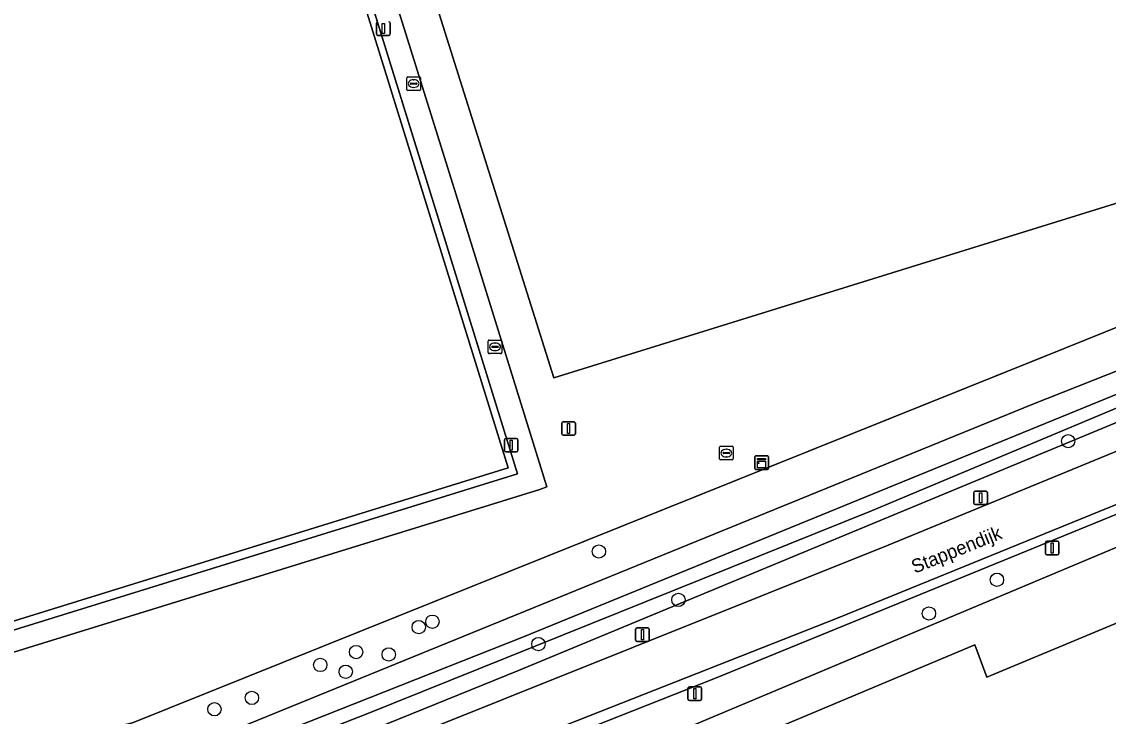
# Model space of a CAD drawing. Extents: x 161090 to 161692, y 379509 to 380907.
# Drawn here: x 161308.9 to 161388.6, y 379764.3 to 379815.2 of the extents above; entities that cross this region are included whole.
import ezdxf

# ---------------------------------------------------------------- set-up
doc = ezdxf.new("R2010")
doc.units = 0
for name, color, linetype in [('IMGEO_Boom', 7, 'Continuous'), ('IMGEO_Fietspad_gesloten', 7, 'Continuous'), ('IMGEO_Groenvoorziening', 7, 'Continuous'), ('IMGEO_Hek', 7, 'Continuous'), ('IMGEO_Kast', 7, 'Continuous'), ('IMGEO_Kolk', 7, 'Continuous'), ('IMGEO_Lichtmast', 7, 'Continuous'), ('IMGEO_Oever', 7, 'Continuous'), ('IMGEO_Openbare_ruimte_label', 7, 'Continuous'), ('IMGEO_Parkeervlak_gesloten', 7, 'Continuous'), ('IMGEO_Rijbaan_lokaal_gesloten', 7, 'Continuous'), ('IMGEO_Rioolput', 7, 'Continuous'), ('IMGEO_Terreindeel_open', 7, 'Continuous'), ('IMGEO_Voetpad_open', 7, 'Continuous'), ('IMGEO_Waterloop', 7, 'Continuous')]:
    doc.layers.add(name, color=color, linetype=linetype)

msp = doc.modelspace()

# ---------------------------------------------------------------- linework, layer by layer
at = {"layer": 'IMGEO_Boom'}
for centre in [(161385.637, 379784.44), (161351.238, 379776.349), (161380.42, 379774.272), (161357.066, 379772.8), (161375.433, 379771.801), (161339.03, 379771.2), (161338.031, 379770.803), (161346.802, 379769.558), (161333.443, 379768.976), (161335.83, 379768.8), (161330.817, 379768.025), (161332.677, 379767.53), (161325.801, 379765.614), (161323.059, 379764.777)]:
    msp.add_circle(centre, 0.489, dxfattribs=at)
at = {"layer": 'IMGEO_Fietspad_gesloten'}
for points in [[(161217.63, 379728.601), (161261.386, 379738.685), (161308.111, 379750), (161320.623, 379753.03), (161330.613, 379756.284), (161333.8, 379757.687), (161368.776, 379771.487), (161387.909, 379779.27), (161415.666, 379790.561)], [(161407.443, 379791.212), (161386.356, 379782.534), (161372.453, 379776.813), (161325.661, 379758.067), (161323.089, 379757.248), (161318.2, 379756.091), (161302.182, 379751.792), (161294.533, 379750), (161230.315, 379734.955)]]:
    msp.add_lwpolyline(points, dxfattribs=at)
at = {"layer": 'IMGEO_Groenvoorziening'}
for points in [[(161407.333, 379882.123), (161377.631, 379872.865), (161377.083, 379874.601), (161374.902, 379873.923), (161375.596, 379871.724), (161373.493, 379871.07), (161372.799, 379873.269), (161370.509, 379872.557), (161371.048, 379870.8), (161341.341, 379861.559), (161340.782, 379863.315), (161333.233, 379860.926), (161323.473, 379857.884), (161325.421, 379851.624), (161340.534, 379803.282), (161347.426, 379781.085), (161346.908, 379780.9), (161282.797, 379761.057), (161284.027, 379756.207), (161284.135, 379755.78), (161317.062, 379763.781), (161383.819, 379790.615), (161442.415, 379814.263)], [(161442.415, 379814.263), (161383.819, 379790.615), (161317.062, 379763.781), (161284.135, 379755.78), (161259.936, 379750), (161224.74, 379740.671)], [(161321.194, 379761.932), (161383.047, 379787.15), (161437.336, 379808.629), (161438.26, 379805.933), (161414.978, 379796.508), (161345.338, 379767.612), (161322.581, 379758.384), (161307.399, 379754.371), (161244.228, 379739.369), (161215.479, 379732.972)], [(161180.807, 379761.477), (161184.615, 379755.126), (161189.385, 379745.645), (161194.335, 379735.113), (161197.105, 379730.453), (161201.159, 379723.634), (161202.937, 379724.063), (161210.481, 379725.863), (161210.245, 379726.978), (161204.585, 379725.735), (161202.141, 379725.056), (161199.88, 379730.004), (161200.37, 379730.456), (161211.43, 379731.076), (161230.315, 379734.955), (161294.533, 379750), (161302.182, 379751.792), (161318.2, 379756.091), (161323.089, 379757.248), (161325.661, 379758.067), (161372.453, 379776.813), (161386.356, 379782.534), (161407.443, 379791.212)], [(161415.916, 379790.022), (161359.784, 379767.053), (161334.748, 379757.161), (161323.449, 379753.122), (161314.492, 379750.449), (161260.228, 379737.49), (161228.423, 379730.143), (161214.473, 379726.815), (161214.755, 379725.892), (161216.77, 379726.358), (161281.548, 379741.341), (161281.646, 379741.364), (161304.908, 379746.911), (161319.404, 379750.447), (161326.887, 379752.243), (161336.716, 379754.602), (161350.416, 379760.36), (161396.996, 379779.937)]]:
    msp.add_lwpolyline(points, dxfattribs=at)
for points in [[(161420.503, 379878.307), (161328.846, 379849.835), (161338.143, 379820.234), (161347.925, 379789.089), (161439.346, 379817.487)], [(161439.346, 379817.487), (161347.925, 379789.089), (161338.143, 379820.234), (161328.846, 379849.835), (161420.503, 379878.307)], [(161214.16, 379727.839), (161214.473, 379726.815), (161228.423, 379730.143), (161260.228, 379737.49), (161314.492, 379750.449), (161323.449, 379753.122), (161334.748, 379757.161), (161359.784, 379767.053), (161415.916, 379790.022), (161415.666, 379790.561), (161387.909, 379779.27), (161368.776, 379771.487), (161333.8, 379757.687), (161330.613, 379756.284), (161320.623, 379753.03), (161308.111, 379750), (161261.386, 379738.685), (161217.63, 379728.601)]]:
    msp.add_lwpolyline(points, close=True, dxfattribs=at)
at = {"layer": 'IMGEO_Hek'}
for points in [[(161315.726, 379877.436), (161345.273, 379782.041)], [(161437.337, 379812.165), (161426.879, 379807.924), (161317.062, 379763.781)], [(161415.916, 379790.022), (161359.784, 379767.053), (161334.748, 379757.161), (161323.449, 379753.122), (161314.492, 379750.449), (161260.228, 379737.49), (161228.423, 379730.143), (161214.473, 379726.815)], [(161345.273, 379782.041), (161288.749, 379764.513)]]:
    msp.add_lwpolyline(points, dxfattribs=at)
at = {"layer": 'IMGEO_Kast'}
for p, q in [((161362.74, 379783.367), (161363.581, 379783.367)), ((161363.581, 379783.367), (161362.74, 379783.367)), ((161362.665, 379782.442), (161362.665, 379783.283)), ((161362.665, 379783.283), (161362.665, 379782.442)), ((161363.665, 379783.292), (161363.665, 379782.451)), ((161363.665, 379782.451), (161363.665, 379783.292)), ((161363.59, 379782.367), (161362.749, 379782.367)), ((161362.749, 379782.367), (161363.59, 379782.367))]:
    msp.add_line(p, q, dxfattribs=at)
for points in [[(161362.86, 379783.157), (161363.46, 379783.157), (161363.46, 379783.072), (161362.86, 379783.072), (161362.86, 379783.157)], [(161362.86, 379782.982), (161363.46, 379782.982), (161363.46, 379782.493), (161362.86, 379782.493), (161362.86, 379782.982)]]:
    msp.add_lwpolyline(points, dxfattribs=at)
msp.add_circle((161362.944, 379782.831), 0.0377, dxfattribs=at)
for centre, start, end in [((161362.743, 379783.289), 92.4484, 184.28452), ((161362.743, 379783.289), 92.4484, 184.28452), ((161363.587, 379783.289), 2.4484, 94.28452), ((161363.587, 379783.289), 2.4484, 94.28452), ((161362.743, 379782.445), 182.4484, 274.28452), ((161362.743, 379782.445), 182.4484, 274.28452), ((161363.587, 379782.445), 272.4484, 4.28452), ((161363.587, 379782.445), 272.4484, 4.28452)]:
    msp.add_arc(centre, 0.0779, start, end, dxfattribs=at)
at = {"layer": 'IMGEO_Kolk'}
for p, q in [((161337.161, 379810.234), (161337.161, 379811.086)), ((161337.236, 379811.16), (161338.088, 379811.16)), ((161337.42, 379810.654), (161337.42, 379810.666)), ((161337.858, 379810.617), (161337.46, 379810.617)), ((161337.463, 379810.703), (161337.861, 379810.703)), ((161337.649, 379810.94), (161337.674, 379810.94)), ((161337.904, 379810.666), (161337.904, 379810.654)), ((161338.162, 379811.086), (161338.162, 379810.234)), ((161338.088, 379810.16), (161337.236, 379810.16)), ((161337.672, 379810.38), (161337.647, 379810.38)), ((161343.125, 379790.93), (161343.125, 379791.782)), ((161343.2, 379791.856), (161344.052, 379791.856)), ((161343.384, 379791.35), (161343.384, 379791.362)), ((161343.822, 379791.313), (161343.424, 379791.313)), ((161343.427, 379791.399), (161343.825, 379791.399)), ((161343.613, 379791.636), (161343.638, 379791.636)), ((161343.868, 379791.362), (161343.868, 379791.35)), ((161344.126, 379791.782), (161344.126, 379790.93)), ((161344.052, 379790.856), (161343.2, 379790.856)), ((161343.636, 379791.076), (161343.611, 379791.076))]:
    msp.add_line(p, q, dxfattribs=at)
for points in [[(161337.161, 379810.234), (161337.161, 379811.086)], [(161337.236, 379811.16), (161338.088, 379811.16)], [(161338.162, 379811.086), (161338.162, 379810.234)], [(161338.088, 379810.16), (161337.236, 379810.16)], [(161343.125, 379790.93), (161343.125, 379791.782)], [(161343.2, 379791.856), (161344.052, 379791.856)], [(161344.126, 379791.782), (161344.126, 379790.93)], [(161344.052, 379790.856), (161343.2, 379790.856)]]:
    msp.add_lwpolyline(points, dxfattribs=at)
for centre, radius, start, end in [((161337.238, 379811.084), 0.0765, 91.55205, 178.44795), ((161337.238, 379811.084), 0.0765, 91.55205, 178.44795), ((161337.46, 379810.663), 0.0403, 85.87752, 175.75265), ((161337.457, 379810.653), 0.0366, 178.93798, 274.71019), ((161337.861, 379810.66), 0.043, 264.86636, 352.45326), ((161337.865, 379810.665), 0.0386, 1.73085, 96.63898), ((161338.086, 379811.084), 0.0765, 1.55205, 88.44795), ((161338.086, 379811.084), 0.0765, 1.55205, 88.44795), ((161337.238, 379810.236), 0.0765, 181.55205, 268.44795), ((161337.238, 379810.236), 0.0765, 181.55205, 268.44795), ((161338.086, 379810.236), 0.0765, 271.55205, 358.44795), ((161338.086, 379810.236), 0.0765, 271.55205, 358.44795), ((161343.202, 379791.78), 0.0765, 91.55205, 178.44795), ((161343.202, 379791.78), 0.0765, 91.55205, 178.44795), ((161343.424, 379791.359), 0.0403, 85.87752, 175.75265), ((161343.421, 379791.349), 0.0366, 178.93798, 274.71019), ((161343.825, 379791.356), 0.043, 264.86636, 352.45326), ((161343.829, 379791.361), 0.0386, 1.73085, 96.63898), ((161344.05, 379791.78), 0.0765, 1.55205, 88.44795), ((161344.05, 379791.78), 0.0765, 1.55205, 88.44795), ((161343.202, 379790.932), 0.0765, 181.55205, 268.44795), ((161343.202, 379790.932), 0.0765, 181.55205, 268.44795), ((161344.05, 379790.932), 0.0765, 271.55205, 358.44795), ((161344.05, 379790.932), 0.0765, 271.55205, 358.44795)]:
    msp.add_arc(centre, radius, start, end, dxfattribs=at)
for centre, major_axis, ratio, start_param, end_param in [((161337.648, 379810.66), (-0.387, 0.002), 0.722429, 4.712389, 7.853982), ((161337.673, 379810.66), (-0.39, 0.002), 0.717154, 1.570796, 4.712389), ((161343.612, 379791.356), (-0.387, 0.002), 0.722429, 4.712389, 7.853982), ((161343.637, 379791.356), (-0.39, 0.002), 0.717154, 1.570796, 4.712389)]:
    msp.add_ellipse(centre, major_axis=major_axis, ratio=ratio, start_param=start_param, end_param=end_param, dxfattribs=at)
at = {"layer": 'IMGEO_Lichtmast'}
for p, q in [((161334.942, 379814.3), (161334.942, 379815.1)), ((161334.942, 379815.1), (161334.942, 379814.3)), ((161335.932, 379815.1), (161335.932, 379814.3)), ((161335.932, 379814.3), (161335.932, 379815.1)), ((161335.832, 379814.2), (161335.042, 379814.2)), ((161335.042, 379814.2), (161335.832, 379814.2)), ((161348.522, 379784.968), (161348.522, 379785.768)), ((161348.522, 379785.768), (161348.522, 379784.968)), ((161348.622, 379785.868), (161349.412, 379785.868)), ((161349.412, 379785.868), (161348.622, 379785.868)), ((161349.512, 379785.768), (161349.512, 379784.968)), ((161349.512, 379784.968), (161349.512, 379785.768)), ((161344.309, 379783.746), (161344.309, 379784.546)), ((161344.309, 379784.546), (161344.309, 379783.746)), ((161344.409, 379784.646), (161345.199, 379784.646)), ((161345.199, 379784.646), (161344.409, 379784.646)), ((161345.299, 379784.546), (161345.299, 379783.746)), ((161345.299, 379783.746), (161345.299, 379784.546)), ((161349.412, 379784.868), (161348.622, 379784.868)), ((161348.622, 379784.868), (161349.412, 379784.868)), ((161345.199, 379783.646), (161344.409, 379783.646)), ((161344.409, 379783.646), (161345.199, 379783.646)), ((161378.727, 379779.884), (161378.727, 379780.684)), ((161378.727, 379780.684), (161378.727, 379779.884)), ((161378.827, 379780.784), (161379.617, 379780.784)), ((161379.617, 379780.784), (161378.827, 379780.784)), ((161379.717, 379780.684), (161379.717, 379779.884)), ((161379.717, 379779.884), (161379.717, 379780.684)), ((161379.617, 379779.784), (161378.827, 379779.784)), ((161378.827, 379779.784), (161379.617, 379779.784)), ((161383.964, 379776.199), (161383.964, 379776.999)), ((161383.964, 379776.999), (161383.964, 379776.199)), ((161384.064, 379777.099), (161384.854, 379777.099)), ((161384.854, 379777.099), (161384.064, 379777.099)), ((161384.954, 379776.999), (161384.954, 379776.199)), ((161384.954, 379776.199), (161384.954, 379776.999)), ((161384.854, 379776.099), (161384.064, 379776.099)), ((161384.064, 379776.099), (161384.854, 379776.099)), ((161353.93, 379769.842), (161353.93, 379770.642)), ((161353.93, 379770.642), (161353.93, 379769.842)), ((161354.03, 379770.742), (161354.82, 379770.742)), ((161354.82, 379770.742), (161354.03, 379770.742)), ((161354.92, 379770.642), (161354.92, 379769.842)), ((161354.92, 379769.842), (161354.92, 379770.642)), ((161354.82, 379769.742), (161354.03, 379769.742)), ((161354.03, 379769.742), (161354.82, 379769.742)), ((161357.77, 379765.52), (161357.77, 379766.32)), ((161357.77, 379766.32), (161357.77, 379765.52)), ((161357.87, 379766.42), (161358.66, 379766.42)), ((161358.66, 379766.42), (161357.87, 379766.42)), ((161358.76, 379766.32), (161358.76, 379765.52)), ((161358.76, 379765.52), (161358.76, 379766.32)), ((161358.66, 379765.42), (161357.87, 379765.42)), ((161357.87, 379765.42), (161358.66, 379765.42))]:
    msp.add_line(p, q, dxfattribs=at)
for points in [[(161335.362, 379815.075), (161335.512, 379815.075), (161335.512, 379814.325), (161335.362, 379814.325), (161335.362, 379815.075)], [(161348.942, 379785.743), (161349.092, 379785.743), (161349.092, 379784.993), (161348.942, 379784.993), (161348.942, 379785.743)], [(161344.729, 379784.521), (161344.879, 379784.521), (161344.879, 379783.771), (161344.729, 379783.771), (161344.729, 379784.521)], [(161379.147, 379780.659), (161379.297, 379780.659), (161379.297, 379779.909), (161379.147, 379779.909), (161379.147, 379780.659)], [(161384.384, 379776.974), (161384.534, 379776.974), (161384.534, 379776.224), (161384.384, 379776.224), (161384.384, 379776.974)], [(161354.35, 379770.617), (161354.5, 379770.617), (161354.5, 379769.867), (161354.35, 379769.867), (161354.35, 379770.617)], [(161358.19, 379766.295), (161358.34, 379766.295), (161358.34, 379765.545), (161358.19, 379765.545), (161358.19, 379766.295)]]:
    msp.add_lwpolyline(points, dxfattribs=at)
for centre, start, end in [((161335.042, 379815.1), 90, 180), ((161335.042, 379815.1), 90, 180), ((161335.832, 379815.1), 0, 90), ((161335.832, 379815.1), 360, 90), ((161335.042, 379814.3), 180, 270), ((161335.042, 379814.3), 180, 270), ((161335.832, 379814.3), 270, 0), ((161335.832, 379814.3), 270, 0), ((161348.622, 379785.768), 90, 180), ((161348.622, 379785.768), 90, 180), ((161349.412, 379785.768), 0, 90), ((161349.412, 379785.768), 360, 90), ((161348.622, 379784.968), 180, 270), ((161348.622, 379784.968), 180, 270), ((161349.412, 379784.968), 270, 0), ((161349.412, 379784.968), 270, 0), ((161344.409, 379784.546), 90, 180), ((161344.409, 379784.546), 90, 180), ((161345.199, 379784.546), 0, 90), ((161345.199, 379784.546), 360, 90), ((161344.409, 379783.746), 180, 270), ((161344.409, 379783.746), 180, 270), ((161345.199, 379783.746), 270, 0), ((161345.199, 379783.746), 270, 0), ((161378.827, 379780.684), 90, 180), ((161378.827, 379780.684), 90, 180), ((161379.617, 379780.684), 0, 90), ((161379.617, 379780.684), 360, 90), ((161378.827, 379779.884), 180, 270), ((161378.827, 379779.884), 180, 270), ((161379.617, 379779.884), 270, 0), ((161379.617, 379779.884), 270, 0), ((161384.064, 379776.999), 90, 180), ((161384.064, 379776.999), 90, 180), ((161384.854, 379776.999), 0, 90), ((161384.854, 379776.999), 360, 90), ((161384.064, 379776.199), 180, 270), ((161384.064, 379776.199), 180, 270), ((161384.854, 379776.199), 270, 0), ((161384.854, 379776.199), 270, 0), ((161354.03, 379770.642), 90, 180), ((161354.03, 379770.642), 90, 180), ((161354.82, 379770.642), 0, 90), ((161354.82, 379770.642), 360, 90), ((161354.03, 379769.842), 180, 270), ((161354.03, 379769.842), 180, 270), ((161354.82, 379769.842), 270, 0), ((161354.82, 379769.842), 270, 0), ((161357.87, 379766.32), 90, 180), ((161357.87, 379766.32), 90, 180), ((161358.66, 379766.32), 0, 90), ((161358.66, 379766.32), 360, 90), ((161357.87, 379765.52), 180, 270), ((161357.87, 379765.52), 180, 270), ((161358.66, 379765.52), 270, 0), ((161358.66, 379765.52), 270, 0)]:
    msp.add_arc(centre, 0.1, start, end, dxfattribs=at)
at = {"layer": 'IMGEO_Oever'}
for points in [[(161307.399, 379754.371), (161322.581, 379758.384), (161345.338, 379767.612), (161414.978, 379796.508), (161438.26, 379805.933), (161437.336, 379808.629), (161383.047, 379787.15), (161321.194, 379761.932), (161295.619, 379755.673), (161234.616, 379741.43), (161209.026, 379735.652)], [(161209.828, 379734.106), (161253.524, 379743.962), (161280.711, 379750.533), (161313.565, 379758.418), (161319.274, 379759.897), (161322.067, 379760.718), (161345.722, 379770.082), (161377.919, 379783.264), (161415.988, 379798.829), (161436.933, 379807.33), (161437.303, 379806.344), (161408.802, 379795.092), (161371.225, 379779.322), (161334.181, 379764.414), (161322.108, 379759.712), (161320.444, 379759.342), (161312.949, 379757.494), (161293.093, 379752.607), (161257.077, 379743.942), (161210.131, 379732.941)]]:
    msp.add_lwpolyline(points, dxfattribs=at)
at = {"layer": 'IMGEO_Parkeervlak_gesloten'}
msp.add_lwpolyline([(161442.363, 379783.593), (161442.348, 379786.735), (161416.941, 379788.17), (161396.996, 379779.937), (161350.416, 379760.36), (161351.281, 379757.944), (161378.797, 379769.491), (161379.671, 379767.143), (161406.243, 379778.203), (161405.758, 379779.385), (161417.67, 379784.271), (161442.331, 379782.871)], dxfattribs=at)
at = {"layer": 'IMGEO_Rijbaan_lokaal_gesloten'}
msp.add_lwpolyline([(161406.243, 379778.203), (161379.671, 379767.143), (161378.797, 379769.491), (161351.281, 379757.944), (161350.416, 379760.36), (161336.716, 379754.602), (161326.887, 379752.243), (161327.54, 379749.873), (161321.727, 379748.473), (161323.599, 379747.342), (161286.161, 379738.464), (161281.646, 379741.364), (161281.548, 379741.341), (161281.952, 379739.475), (161252.424, 379732.547), (161217.161, 379724.368), (161216.77, 379726.358), (161214.755, 379725.892), (161214.473, 379726.815), (161210.481, 379725.863), (161210.689, 379724.879), (161208.4, 379724.379)], dxfattribs=at)
at = {"layer": 'IMGEO_Rioolput'}
for p, q in [((161360.081, 379783.14), (161360.081, 379783.992)), ((161360.156, 379784.066), (161361.008, 379784.066)), ((161360.34, 379783.56), (161360.34, 379783.572)), ((161360.778, 379783.523), (161360.38, 379783.523)), ((161360.383, 379783.609), (161360.781, 379783.609)), ((161360.569, 379783.846), (161360.594, 379783.846)), ((161360.824, 379783.572), (161360.824, 379783.56)), ((161361.082, 379783.992), (161361.082, 379783.14)), ((161361.008, 379783.066), (161360.156, 379783.066)), ((161360.592, 379783.286), (161360.567, 379783.286))]:
    msp.add_line(p, q, dxfattribs=at)
for points in [[(161360.081, 379783.14), (161360.081, 379783.992)], [(161360.156, 379784.066), (161361.008, 379784.066)], [(161361.082, 379783.992), (161361.082, 379783.14)], [(161361.008, 379783.066), (161360.156, 379783.066)]]:
    msp.add_lwpolyline(points, dxfattribs=at)
for centre, radius, start, end in [((161360.158, 379783.99), 0.0765, 91.55205, 178.44795), ((161360.158, 379783.99), 0.0765, 91.55205, 178.44795), ((161360.38, 379783.569), 0.0403, 85.87752, 175.75265), ((161360.377, 379783.559), 0.0366, 178.93798, 274.71019), ((161360.781, 379783.566), 0.043, 264.86636, 352.45326), ((161360.785, 379783.571), 0.0386, 1.73085, 96.63898), ((161361.006, 379783.99), 0.0765, 1.55205, 88.44795), ((161361.006, 379783.99), 0.0765, 1.55205, 88.44795), ((161360.158, 379783.142), 0.0765, 181.55205, 268.44795), ((161360.158, 379783.142), 0.0765, 181.55205, 268.44795), ((161361.006, 379783.142), 0.0765, 271.55205, 358.44795), ((161361.006, 379783.142), 0.0765, 271.55205, 358.44795)]:
    msp.add_arc(centre, radius, start, end, dxfattribs=at)
for centre, major_axis, ratio, start_param, end_param in [((161360.568, 379783.566), (-0.387, 0.002), 0.722429, 4.712389, 7.853982), ((161360.593, 379783.566), (-0.39, 0.002), 0.717154, 1.570796, 4.712389)]:
    msp.add_ellipse(centre, major_axis=major_axis, ratio=ratio, start_param=start_param, end_param=end_param, dxfattribs=at)
at = {"layer": 'IMGEO_Terreindeel_open'}
msp.add_lwpolyline([(161315.4, 379876.688), (161259.804, 379859.465), (161288.984, 379765.251), (161344.596, 379782.479)], close=True, dxfattribs=at)
at = {"layer": 'IMGEO_Voetpad_open'}
for points in [[(161345.273, 379782.041), (161321.936, 379857.387), (161315.726, 379877.436), (161259.154, 379859.946), (161259.297, 379859.485), (161286.836, 379770.682), (161288.749, 379764.513)], [(161288.984, 379765.251), (161259.804, 379859.465), (161315.4, 379876.688), (161344.596, 379782.479)]]:
    msp.add_lwpolyline(points, close=True, dxfattribs=at)
msp.add_lwpolyline([(161222.404, 379742.64), (161249.847, 379751.021), (161249.639, 379751.726), (161254.818, 379753.256), (161255.005, 379752.623), (161282.797, 379761.057), (161346.908, 379780.9), (161347.426, 379781.085), (161340.534, 379803.282), (161325.421, 379851.624), (161323.473, 379857.884), (161321.936, 379857.387), (161345.273, 379782.041), (161288.749, 379764.513), (161281.179, 379762.159), (161241.872, 379750)], dxfattribs=at)
at = {"layer": 'IMGEO_Waterloop'}
msp.add_lwpolyline([(161293.093, 379752.607), (161312.949, 379757.494), (161320.444, 379759.342), (161322.108, 379759.712), (161334.181, 379764.414), (161371.225, 379779.322), (161408.802, 379795.092), (161437.303, 379806.344), (161436.933, 379807.33), (161415.988, 379798.829), (161377.919, 379783.264), (161345.722, 379770.082), (161322.067, 379760.718), (161319.274, 379759.897), (161313.565, 379758.418), (161280.711, 379750.533), (161253.524, 379743.962), (161209.828, 379734.106)], dxfattribs=at)

# ---------------------------------------------------------------- texts
at = {"layer": 'IMGEO_Openbare_ruimte_label'}
msp.add_text('Stappendijk', height=1, rotation=21.89715, dxfattribs=at).set_placement((161374.388, 379774.715))

doc.saveas('drawing.dxf')
